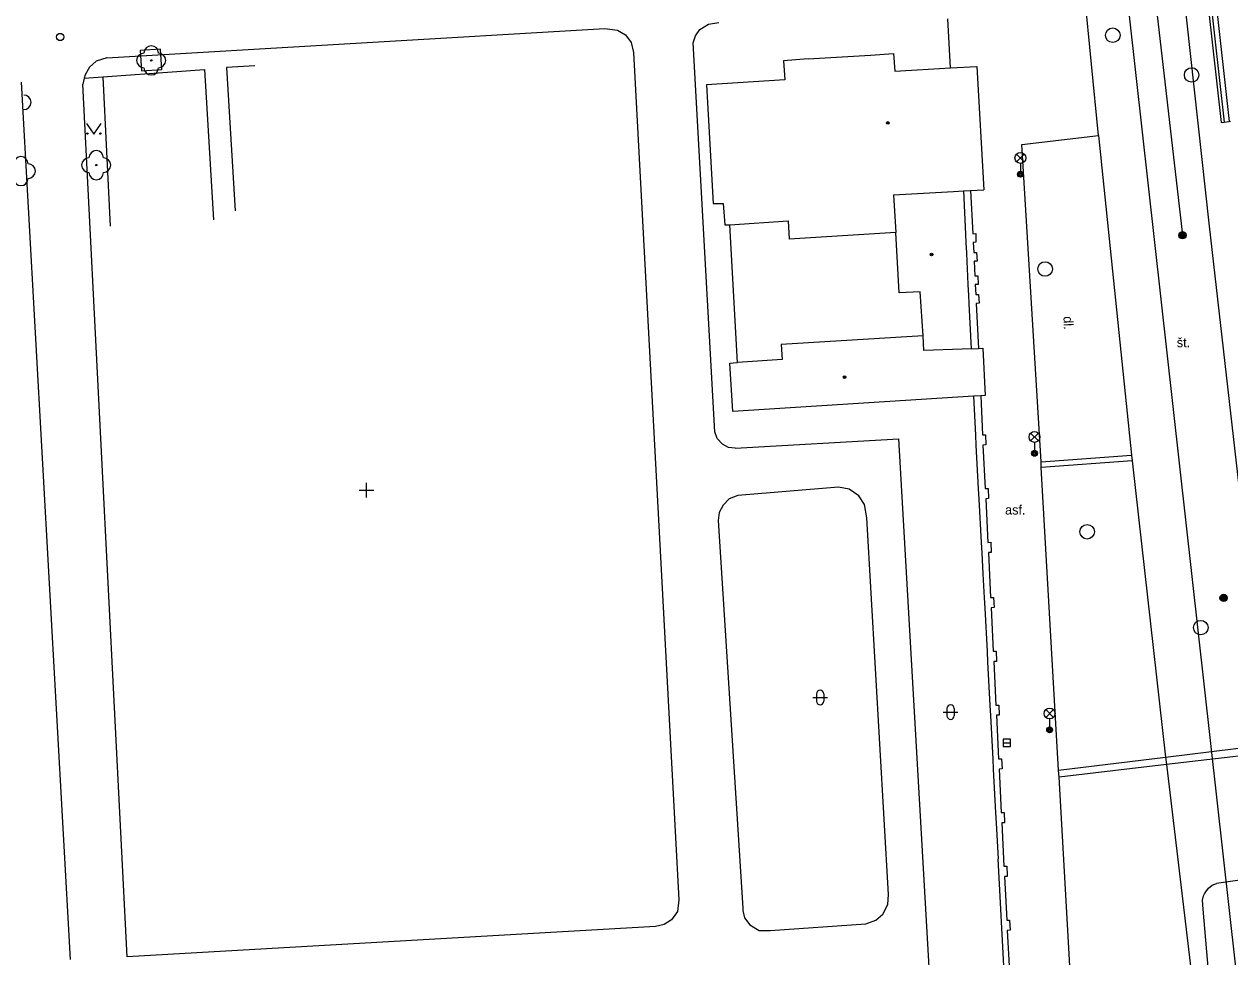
# Model space of a CAD drawing. Extents: x -599951 to -598963, y -1164095 to -1162939.
# Drawn here: x -599295.3 to -599212.4, y -1163429.4 to -1163365.3 of the extents above; entities that cross this region are included whole.
import ezdxf

# ---------------------------------------------------------------- set-up
doc = ezdxf.new("R2010")
doc.units = 0
for name, color, linetype in [('Level 11', 7, 'Continuous'), ('Level 13', 7, 'Continuous'), ('Level 22', 7, 'Continuous'), ('Level 25', 7, 'Continuous'), ('Level 27', 7, 'Continuous'), ('Level 28', 7, 'Continuous'), ('Level 33', 7, 'Continuous'), ('Level 36', 7, 'Continuous'), ('Level 39', 7, 'Continuous'), ('Level 40', 7, 'Continuous'), ('Level 5', 7, 'Continuous'), ('Level 51', 7, 'Continuous'), ('Level 54', 7, 'Continuous'), ('Level 7', 7, 'Continuous'), ('Level 8', 7, 'Continuous'), ('Level 9', 7, 'Continuous')]:
    doc.layers.add(name, color=color, linetype=linetype)

msp = doc.modelspace()

# ---------------------------------------------------------------- linework, layer by layer
at = {"layer": 'Level 11'}
for points in [[(-599221.47, -1163372.95), (-599225.31, -1163333.69), (-599226.05, -1163325.62), (-599227.29, -1163309.9), (-599225.95, -1163309.35), (-599226.08, -1163307.7)], [(-599219.16, -1163307.2), (-599218.93, -1163311.13), (-599218.91, -1163311.5), (-599217.92, -1163323.83), (-599216.92, -1163336.16), (-599215.08, -1163353.62), (-599213.02, -1163372.05), (-599212.82, -1163372.02)], [(-599214.89, -1163353.58), (-599212.82, -1163372.02)], [(-599214.5, -1163353.81), (-599212.47, -1163371.97)], [(-599212.82, -1163372.02), (-599212.47, -1163371.97)], [(-599212.47, -1163371.97), (-599212.39, -1163371.96)], [(-599226.72, -1163373.56), (-599221.47, -1163372.95)], [(-599221.47, -1163372.95), (-599219.19, -1163394.91)], [(-599225.41, -1163395.37), (-599226.72, -1163373.56)], [(-599246.27, -1163388.54), (-599246.79, -1163379.08)], [(-599225.41, -1163395.37), (-599219.19, -1163394.91)], [(-599219.19, -1163394.91), (-599219.14, -1163395.31)], [(-599225.39, -1163395.77), (-599225.41, -1163395.37)], [(-599219.14, -1163395.31), (-599225.39, -1163395.77)], [(-599224.2, -1163416.56), (-599225.39, -1163395.77)], [(-599219.14, -1163395.31), (-599216.85, -1163415.68)], [(-599216.85, -1163415.68), (-599207.36, -1163414.51)], [(-599224.2, -1163416.56), (-599216.85, -1163415.68)], [(-599216.85, -1163415.68), (-599216.79, -1163416.18)], [(-599207.29, -1163415.09), (-599216.79, -1163416.18)], [(-599216.79, -1163416.18), (-599224.17, -1163417.06)], [(-599216.79, -1163416.18), (-599215.08, -1163430.4)], [(-599224.17, -1163417.06), (-599224.2, -1163416.56)], [(-599223.37, -1163431.24), (-599224.17, -1163417.06)], [(-599227.76, -1163423.17), (-599227.73, -1163423.8), (-599227.73, -1163423.87), (-599227.93, -1163423.88), (-599227.77, -1163426.88), (-599227.57, -1163426.87), (-599227.53, -1163427.57), (-599227.73, -1163427.58), (-599227.58, -1163430.43)], [(-599208.22, -1163423.63), (-599213.36, -1163424.35)], [(-599214.27, -1163426.13), (-599214.313, -1163425.507), (-599214.233, -1163425.203), (-599214.17, -1163425.06), (-599214.09, -1163424.923), (-599213.891, -1163424.68), (-599213.643, -1163424.486), (-599213.36, -1163424.35)], [(-599213.89, -1163430.39), (-599214.27, -1163426.13)]]:
    msp.add_lwpolyline(points, dxfattribs=at)
at = {"layer": 'Level 13'}
for points in [[(-599227.9, -1163250.53), (-599226.6, -1163273.59), (-599224.47, -1163311.15), (-599221.04, -1163349.52), (-599208.62, -1163460.66)], [(-599222.94, -1163267.2), (-599220.64, -1163310.52), (-599217.22, -1163348.54), (-599213.85, -1163379.17), (-599204.7, -1163459.51)]]:
    msp.add_lwpolyline(points, dxfattribs=at)
at = {"layer": 'Level 22'}
for centre in [(-599286.57, -1163367.78), (-599290.35, -1163374.98)]:
    msp.add_circle(centre, 0.05, dxfattribs=at)
for centre, start, end in [((-599286.57, -1163367.28), 0, 180), ((-599287.07, -1163367.78), 90, 270), ((-599286.07, -1163367.78), 270, 90), ((-599286.57, -1163368.28), 180, 0), ((-599295.33, -1163370.66), 270, 90), ((-599290.35, -1163374.48), 0, 180), ((-599295.53, -1163374.89), 0, 180), ((-599295.03, -1163375.39), 270, 90), ((-599290.85, -1163374.98), 90, 270), ((-599289.85, -1163374.98), 270, 90), ((-599295.53, -1163375.89), 180, 0), ((-599290.35, -1163375.48), 180, 0)]:
    msp.add_arc(centre, 0.5, start, end, dxfattribs=at)
at = {"layer": 'Level 25'}
for centre, radius in [((-599215.69, -1163379.8), 0.25), ((-599215.69, -1163379.8), 0.2), ((-599215.69, -1163379.8), 0.15), ((-599215.69, -1163379.8), 0.1), ((-599215.69, -1163379.8), 0.05), ((-599212.86, -1163404.73), 0.25), ((-599212.86, -1163404.73), 0.2), ((-599212.86, -1163404.73), 0.15), ((-599212.86, -1163404.73), 0.1), ((-599212.86, -1163404.73), 0.05)]:
    msp.add_circle(centre, radius, dxfattribs=at)
at = {"layer": 'Level 27'}
msp.add_line((-599228.01, -1163414.7), (-599227.51, -1163414.7), dxfattribs=at)
msp.add_lwpolyline([(-599228.01, -1163414.95), (-599227.51, -1163414.95), (-599227.51, -1163414.45), (-599228.01, -1163414.45)], close=True, dxfattribs=at)
for centre in [(-599220.48, -1163366.05), (-599215.06, -1163368.78), (-599225.13, -1163382.12), (-599222.24, -1163400.18), (-599214.43, -1163406.77)]:
    msp.add_circle(centre, 0.5, dxfattribs=at)
at = {"layer": 'Level 28'}
msp.add_circle((-599292.83, -1163366.17), 0.25, dxfattribs=at)
msp.add_circle((-599292.83, -1163366.17), 0.25, dxfattribs=at)
at = {"layer": 'Level 33'}
for p, q in [((-599227.095, -1163374.75), (-599226.565, -1163374.22)), ((-599227.095, -1163374.22), (-599226.565, -1163374.75)), ((-599226.83, -1163374.86), (-599226.83, -1163375.61)), ((-599226.125, -1163393.93), (-599225.595, -1163393.4)), ((-599226.125, -1163393.4), (-599225.595, -1163393.93)), ((-599225.86, -1163394.04), (-599225.86, -1163394.79)), ((-599225.085, -1163412.94), (-599224.555, -1163412.41)), ((-599225.085, -1163412.41), (-599224.555, -1163412.94)), ((-599224.82, -1163413.05), (-599224.82, -1163413.8))]:
    msp.add_line(p, q, dxfattribs=at)
for centre, radius in [((-599226.83, -1163374.485), 0.375), ((-599226.83, -1163375.61), 0.2), ((-599226.83, -1163375.61), 0.145), ((-599226.83, -1163375.61), 0.0876), ((-599225.86, -1163393.665), 0.375), ((-599225.86, -1163394.79), 0.2), ((-599225.86, -1163394.79), 0.145), ((-599225.86, -1163394.79), 0.0876), ((-599224.82, -1163412.675), 0.375), ((-599224.82, -1163413.8), 0.2), ((-599224.82, -1163413.8), 0.145), ((-599224.82, -1163413.8), 0.0876)]:
    msp.add_circle(centre, radius, dxfattribs=at)
at = {"layer": 'Level 36'}
for p, q in [((-599272.27, -1163397.32), (-599271.27, -1163397.32)), ((-599271.77, -1163397.82), (-599271.77, -1163396.82)), ((-599240.846, -1163411.326), (-599240.846, -1163411.826)), ((-599240.346, -1163411.326), (-599240.346, -1163411.826)), ((-599241.096, -1163411.576), (-599240.096, -1163411.576)), ((-599231.876, -1163412.326), (-599231.876, -1163412.826)), ((-599231.376, -1163412.326), (-599231.376, -1163412.826)), ((-599232.126, -1163412.576), (-599231.126, -1163412.576))]:
    msp.add_line(p, q, dxfattribs=at)
msp.add_lwpolyline([(-599291.01, -1163372.11), (-599290.51, -1163372.86), (-599290.01, -1163372.11)], dxfattribs=at)
for centre in [(-599290.96, -1163372.81), (-599290.061, -1163372.81)]:
    msp.add_circle(centre, 0.05, dxfattribs=at)
for centre, start, end in [((-599240.596, -1163411.326), 0, 180), ((-599240.596, -1163411.826), 180, 0), ((-599231.626, -1163412.326), 0, 180), ((-599231.626, -1163412.826), 180, 0)]:
    msp.add_arc(centre, 0.25, start, end, dxfattribs=at)
at = {"layer": 'Level 39'}
for centre, radius in [((-599235.94, -1163372.08), 0.09), ((-599235.94, -1163372.08), 0.0398), ((-599232.93, -1163381.12), 0.09), ((-599232.93, -1163381.12), 0.0398), ((-599238.91, -1163389.55), 0.09), ((-599238.91, -1163389.55), 0.0398)]:
    msp.add_circle(centre, radius, dxfattribs=at)
at = {"layer": 'Level 5'}
for points in [[(-599241.42, -1163367.67), (-599237.14, -1163367.43)], [(-599237.14, -1163367.43), (-599235.56, -1163367.3)], [(-599235.56, -1163367.3), (-599235.46, -1163368.51)], [(-599241.42, -1163367.67), (-599243.11, -1163367.81)], [(-599243.11, -1163367.81), (-599243.03, -1163369.12)], [(-599235.46, -1163368.51), (-599231.64, -1163368.3)], [(-599231.64, -1163368.3), (-599229.82, -1163368.2)], [(-599229.82, -1163368.2), (-599229.35, -1163376.68)], [(-599243.03, -1163369.12), (-599248.41, -1163369.47)], [(-599248.41, -1163369.47), (-599247.94, -1163377.61)], [(-599230.75, -1163376.75), (-599230.25, -1163376.73)], [(-599230.25, -1163376.73), (-599229.35, -1163376.68)], [(-599235.55, -1163377.02), (-599231.42, -1163376.79)], [(-599235.55, -1163377.02), (-599235.38, -1163379.6)], [(-599231.42, -1163376.79), (-599230.75, -1163376.75)], [(-599230.75, -1163376.75), (-599230.6, -1163379.72)], [(-599247.94, -1163377.61), (-599247.26, -1163377.61)], [(-599247.26, -1163377.61), (-599247.15, -1163379.08)], [(-599247.15, -1163379.08), (-599246.79, -1163379.08)], [(-599246.79, -1163379.08), (-599242.79, -1163378.81)], [(-599242.79, -1163378.81), (-599242.71, -1163380.07)], [(-599235.38, -1163379.6), (-599242.71, -1163380.07)], [(-599235.16, -1163383.75), (-599235.38, -1163379.6)], [(-599230.6, -1163379.72), (-599230.57, -1163380.31)], [(-599230.57, -1163380.31), (-599230.54, -1163381.01)], [(-599230.54, -1163381.01), (-599230.51, -1163381.61)], [(-599230.51, -1163381.61), (-599230.46, -1163382.61)], [(-599230.46, -1163382.61), (-599230.43, -1163383.21)], [(-599230.43, -1163383.21), (-599230.4, -1163383.91)], [(-599233.71, -1163383.69), (-599235.16, -1163383.75)], [(-599233.5, -1163386.71), (-599233.71, -1163383.69)], [(-599230.4, -1163383.91), (-599230.37, -1163384.51)], [(-599230.37, -1163384.51), (-599230.21, -1163387.61)], [(-599243.26, -1163387.32), (-599243.2, -1163388.35), (-599246.27, -1163388.54)], [(-599233.5, -1163386.71), (-599243.26, -1163387.32)], [(-599233.46, -1163387.73), (-599233.5, -1163386.71)], [(-599230.84, -1163387.63), (-599233.46, -1163387.73)], [(-599230.21, -1163387.61), (-599230.84, -1163387.63)], [(-599230.21, -1163387.61), (-599229.71, -1163387.59)], [(-599229.71, -1163387.59), (-599229.41, -1163387.57)], [(-599229.41, -1163387.57), (-599229.25, -1163390.82)], [(-599246.81, -1163388.6), (-599246.56, -1163388.56)], [(-599246.59, -1163391.92), (-599246.81, -1163388.6)], [(-599246.56, -1163388.56), (-599246.27, -1163388.54)], [(-599229.25, -1163390.82), (-599229.55, -1163390.84)], [(-599230.06, -1163390.87), (-599246.59, -1163391.92)], [(-599229.55, -1163390.84), (-599230.06, -1163390.87)]]:
    msp.add_lwpolyline(points, dxfattribs=at)
at = {"layer": 'Level 51'}
for points in [[(-599289.61, -1163367.6), (-599290.36, -1163367.84), (-599290.8, -1163368.25), (-599291.12, -1163368.78), (-599291.17, -1163369)], [(-599291.17, -1163369), (-599291.27, -1163369.42)]]:
    msp.add_lwpolyline(points, dxfattribs=at)
at = {"layer": 'Level 54'}
for points in [[(-599289.61, -1163367.6), (-599255.38, -1163365.59)], [(-599255.38, -1163365.59), (-599254.52, -1163365.69)], [(-599254.52, -1163365.69), (-599253.98, -1163366.03)], [(-599249.17, -1163366.08), (-599248.86, -1163365.66)], [(-599248.86, -1163365.66), (-599248.26, -1163365.29)], [(-599248.26, -1163365.29), (-599247.55, -1163365.18)], [(-599253.98, -1163366.03), (-599253.57, -1163366.56)], [(-599253.57, -1163366.56), (-599253.42, -1163367.24)], [(-599249.33, -1163366.57), (-599249.17, -1163366.08)], [(-599247.84, -1163393.32), (-599249.33, -1163366.57)], [(-599285.93, -1163367.01), (-599287.33, -1163367.11)], [(-599287.33, -1163367.11), (-599287.23, -1163368.5)], [(-599285.83, -1163368.41), (-599285.93, -1163367.01)], [(-599253.42, -1163367.24), (-599250.31, -1163425.48)], [(-599289.89, -1163368.91), (-599282.91, -1163368.4)], [(-599287.23, -1163368.5), (-599285.83, -1163368.41)], [(-599282.91, -1163368.4), (-599282.29, -1163378.74)], [(-599279.44, -1163368.16), (-599281.4, -1163368.27)], [(-599281.4, -1163368.27), (-599280.81, -1163378.12)], [(-599295.5, -1163369.28), (-599292.15, -1163429.58)], [(-599291.17, -1163369), (-599289.89, -1163368.91)], [(-599289.89, -1163368.91), (-599289.4, -1163379.17)], [(-599288.22, -1163429.4), (-599291.27, -1163369.42)], [(-599247.68, -1163393.76), (-599247.84, -1163393.32)], [(-599247.31, -1163394.16), (-599247.68, -1163393.76)], [(-599246.44, -1163394.43), (-599235.18, -1163393.79)], [(-599232.32, -1163443.68), (-599235.18, -1163393.79)], [(-599246.89, -1163394.39), (-599247.31, -1163394.16)], [(-599246.44, -1163394.43), (-599246.89, -1163394.39)], [(-599239.33, -1163397.11), (-599246.26, -1163397.68)], [(-599238.6, -1163397.25), (-599239.33, -1163397.11)], [(-599237.93, -1163397.71), (-599238.6, -1163397.25)], [(-599246.85, -1163397.92), (-599247.26, -1163398.35)], [(-599246.26, -1163397.68), (-599246.85, -1163397.92)], [(-599237.55, -1163398.3), (-599237.93, -1163397.71)], [(-599247.53, -1163398.86), (-599247.61, -1163399.41)], [(-599247.26, -1163398.35), (-599247.53, -1163398.86)], [(-599237.39, -1163399.22), (-599237.55, -1163398.3)], [(-599247.61, -1163399.41), (-599245.9, -1163426.05)], [(-599235.89, -1163425.12), (-599237.39, -1163399.22)], [(-599227.25, -1163443.42), (-599228.36, -1163422.66)], [(-599250.31, -1163425.48), (-599250.4, -1163426.29)], [(-599235.93, -1163425.81), (-599235.89, -1163425.12)], [(-599250.4, -1163426.29), (-599250.81, -1163426.85)], [(-599245.9, -1163426.05), (-599245.9, -1163426.21)], [(-599245.9, -1163426.21), (-599245.78, -1163426.71)], [(-599236.76, -1163426.88), (-599236.28, -1163426.47)], [(-599236.28, -1163426.47), (-599235.93, -1163425.81)], [(-599251.32, -1163427.19), (-599251.92, -1163427.31)], [(-599250.81, -1163426.85), (-599251.32, -1163427.19)], [(-599245.78, -1163426.71), (-599245.43, -1163427.2)], [(-599245.43, -1163427.2), (-599244.79, -1163427.58)], [(-599244.03, -1163427.58), (-599237.45, -1163427.14)], [(-599237.45, -1163427.14), (-599236.76, -1163426.88)], [(-599251.92, -1163427.31), (-599288.22, -1163429.4)], [(-599244.79, -1163427.58), (-599244.03, -1163427.58)]]:
    msp.add_lwpolyline(points, dxfattribs=at)
at = {"layer": 'Level 7'}
for points in [[(-599230.25, -1163376.73), (-599230.1, -1163379.69), (-599229.9, -1163379.68), (-599229.88, -1163380.28), (-599230.07, -1163380.29), (-599230.04, -1163380.99), (-599229.84, -1163380.98), (-599229.81, -1163381.58), (-599230.01, -1163381.59), (-599229.96, -1163382.59), (-599229.76, -1163382.58), (-599229.73, -1163383.18), (-599229.93, -1163383.19), (-599229.9, -1163383.88), (-599229.7, -1163383.87), (-599229.67, -1163384.47), (-599229.87, -1163384.48), (-599229.71, -1163387.59)], [(-599230.06, -1163390.87), (-599229.92, -1163393.55)], [(-599229.55, -1163390.84), (-599229.43, -1163393.52), (-599229.23, -1163393.51), (-599229.2, -1163394.21), (-599229.4, -1163394.22), (-599229.25, -1163397.21), (-599229.05, -1163397.2), (-599229.01, -1163397.9), (-599229.21, -1163397.91), (-599229.07, -1163400.91), (-599228.87, -1163400.9), (-599228.83, -1163401.6), (-599229.03, -1163401.61), (-599228.88, -1163404.7)], [(-599229.92, -1163393.55), (-599229.88, -1163394.24)], [(-599229.88, -1163394.24), (-599229.72, -1163397.24)], [(-599229.72, -1163397.24), (-599229.68, -1163397.94)], [(-599229.68, -1163397.94), (-599229.52, -1163400.93)], [(-599229.52, -1163400.93), (-599229.49, -1163401.63)], [(-599229.49, -1163401.63), (-599229.41, -1163403.07)], [(-599229.41, -1163403.07), (-599229.32, -1163404.73)], [(-599229.32, -1163404.73), (-599229.28, -1163405.43)], [(-599228.88, -1163404.7), (-599228.68, -1163404.69), (-599228.64, -1163405.39), (-599228.84, -1163405.4), (-599228.69, -1163408.4), (-599228.49, -1163408.39), (-599228.46, -1163409.09), (-599228.66, -1163409.1), (-599228.51, -1163412.09), (-599228.31, -1163412.09), (-599228.28, -1163412.78), (-599228.48, -1163412.79), (-599228.33, -1163415.79), (-599228.13, -1163415.78), (-599228.09, -1163416.48), (-599228.29, -1163416.49), (-599228.15, -1163419.49), (-599227.95, -1163419.48), (-599227.91, -1163420.18), (-599228.11, -1163420.19), (-599227.96, -1163423.18), (-599227.76, -1163423.17)], [(-599229.28, -1163405.43), (-599229.12, -1163408.42)], [(-599229.12, -1163408.42), (-599229.08, -1163409.12)], [(-599229.08, -1163409.12), (-599228.92, -1163412.12)], [(-599228.92, -1163412.12), (-599228.89, -1163412.82)], [(-599228.89, -1163412.82), (-599228.73, -1163415.81)], [(-599228.73, -1163415.81), (-599228.69, -1163416.51)], [(-599228.69, -1163416.51), (-599228.53, -1163419.51)], [(-599228.53, -1163419.51), (-599228.49, -1163420.21)], [(-599228.49, -1163420.21), (-599228.36, -1163422.66)]]:
    msp.add_lwpolyline(points, dxfattribs=at)
at = {"layer": 'Level 8'}
msp.add_lwpolyline([(-599231.64, -1163368.3), (-599231.82, -1163364.92)], dxfattribs=at)
at = {"layer": 'Level 9'}
msp.add_lwpolyline([(-599222.66, -1163309.28), (-599221.3, -1163326.92), (-599218.77, -1163352.93), (-599215.69, -1163379.8)], dxfattribs=at)

# ---------------------------------------------------------------- texts
at = {"layer": 'Level 40'}
msp.add_text('dl.', height=0.65, rotation=271.97, dxfattribs=at).set_placement((-599223.87, -1163385.38))
for s, p in [('št.', (-599216.08, -1163387.5)), ('asf.', (-599227.88, -1163399))]:
    msp.add_text(s, height=0.65, dxfattribs=at).set_placement(p)

doc.saveas('drawing.dxf')
